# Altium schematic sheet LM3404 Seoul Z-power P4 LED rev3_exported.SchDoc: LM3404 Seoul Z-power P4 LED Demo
size A; Author: Chris Richardson; Organization: National Semiconductor; Address1: 2900 Semiconductor Dr.; Address2: MS G1-325; Address3: Santa Clara, CA  95051; Address4: United States; Revision: 1.3; SheetNumber: 1; SheetTotal: 1
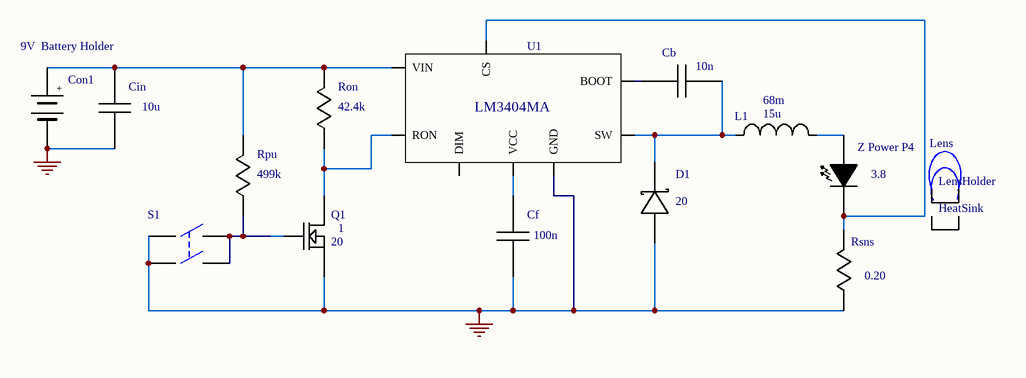
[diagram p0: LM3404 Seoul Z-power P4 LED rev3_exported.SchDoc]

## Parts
Cb  Cap (F): 10n  (hidden comment: VJ0603Y103KXXA)
Cf  Cap (F): 100n  (hidden comment: VJ0603Y104KXXA)
Cin  Cap (F): 10u  (hidden comment: C3216X7R1C106M)
Con1  Comment_1: 9V  Battery Holder  (hidden comment: WB_BATTERY)
D1  Vf (V): 20  (hidden comment: WB_DIODE_SCHOTTKY)
HeatSink  HeatSink  (value not drawn)  (mechanical)
L1  DCR (Ohms): 68m  L (H): 15u  (hidden comment: WB_INDUCTOR)
Lens  Lens Cover  (value not drawn)
LensHolder  Lens Holder  (value not drawn)
Q1  VdsMax (V): 20  IdsMax (A): 1  (hidden comment: WB_N_MOSFET)
Ron  Res (ohm): 42.4k  (hidden comment: CRCW06034222F)
Rpu  Res (ohm): 499k  (hidden comment: CRCW06034993F)
Rsns  Res (ohm): 0.20  (hidden comment: ERJ8BQFR20V)
S1  SW-DPST  (value not drawn)
U1  LM3404MA  (value not drawn)
Z_Power_P4  Power_TotalModule: 3.8  (hidden comment: WB_DIODE_LED)

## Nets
GND: Cf.2 Cin.1 Con1.2(-) D1.1(A) Q1.3(Source) Rsns.2 S1.1(COMMON1) S1.3(COMMON2) U1.4(GND)
NetCb_1: Cb.1 U1.2(BOOT)
NetCb_2: Cb.2 D1.2(K) L1.2 U1.1(SW)
NetCf_1: Cf.1 U1.7(VCC)
NetCin_2: Cin.2 Con1.1(+) Ron.1 Rpu.1 U1.8(VIN)
NetL1_1: L1.1 Z_Power_P4.1(A)
NetQ1_1: Q1.1(Drain) Ron.2 U1.6(RON)
NetQ1_2: Q1.2(Gate) Rpu.2 S1.2(NO1) S1.4(NO2)
NetRsns_1: Rsns.1 U1.5(CS) Z_Power_P4.2(K)

Not connected (* = marked no-connect by the designer): U1 3(DIM)

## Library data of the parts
Cb Cf = VJ0603Y104KXXA: Manufacturer: CUSTOM; VDC (V): 25; Comp Type: Capacitor; Vendor: Vishay-Vitramon; Tolerance (%): 10; TaMin (C): -55; TaMax (C): 125; Polarized: N; Cap_Case: 0603; Symbol Name: WB_CAPACITOR; CompTypeIndex: 30
Cin = VJ0603Y104KXXA: Manufacturer: CUSTOM; VDC (V): 16; Comp Type: Capacitor; Vendor: TDK; TaMin (C): -55; TaMax (C): 125; Polarized: N; Cap_Case: 1206; Symbol Name: WB_CAPACITOR; CompTypeIndex: 30
Con1 = WB_BATTERY: PartNumber: 968K-ND; Manufacturer: CUSTOM; Vendor: Keystone; CompTypeIndex: 30
D1 = WB_DIODE_SCHOTTKY: PartNumber: CMSH2-20M; Manufacturer: CUSTOM; Io (A): 2; Vendor: Central Semi; Type: Shottky Diode; Comp Type: Diode; CompTypeIndex: 40
HeatSink = LEDLensHolder: PartNumber: 374424b00035g; Vendor: Aavid
L1 = WB_INDUCTOR: PartNumber: SLF7045T-M1R5-1PF; Manufacturer: CUSTOM; Vendor: TDK; Imax(A): 1.5; CompTypeIndex: 20
Lens = Lens: PartNumber: KEPL 19806; Manufacturer: CUSTOM; Vendor: Khatod; CompTypeIndex: 20
LensHolder = LEDLensHolder: PartNumber: KE 198; Manufacturer: CUSTOM; Vendor: Khatod; CompTypeIndex: 20
Q1 = WB_N_MOSFET: PartNumber: TN0201K; Manufacturer: CUSTOM; Vendor: Vishay; Comp Type: MOSFET; ChType: N; CompTypeIndex: 51
Ron Rpu = WB_RESISTOR: Manufacturer: CUSTOM; Tolerance (%): 1; Vendor: Vishay; CompTypeIndex: 10
Rsns = WB_RESISTOR: Manufacturer: CUSTOM; Tolerance (%): 1; Vendor: Panasonic; CompTypeIndex: 10
S1 = SW-DPST: PartNumber: KSC2-1-1-J-50SH-LFS; Manufacturer: CUSTOM; Vendor: ITT/Canon; CompTypeIndex: 0
U1 = LM3404MA: Manufacturer: CUSTOM; Vendor: National Semiconductor; base_pn: LM3404; Comp Type: Switcher; CompTypeIndex: 110
Z_Power_P4 = WB_DIODE_LED: PartNumber: W42180-T; Manufacturer: CUSTOM; RJC (C/W): 6.9; Vendor: Seoul Semiconductor; Comp Type: LED; LuminousFlux_PhiV: 80; NumParallelLEDs: 1; Vf (V): 3.25; TJmax (C): 145; CompTypeIndex: 0; Comment_1: W42180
